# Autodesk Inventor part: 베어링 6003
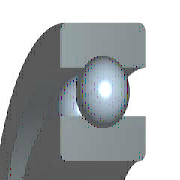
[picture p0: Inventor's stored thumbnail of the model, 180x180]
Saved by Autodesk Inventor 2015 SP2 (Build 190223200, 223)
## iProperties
IsCustomPart: 1
Created: 2009-02
Part Number: 베어링 6003
Material: 강, 연강
Description: 깊은 그루브 볼 베어링
Document SubType Name: Modeling
Standard: KS B 2023
Designer: 한국산업디자인학원
Standards Organization: KS
Language: ko-KR
Size Designation: 6003 - 17 x 35 x 10
Categories: <MemberInstance><Categories><Category DisplayName="샤프트 부품" InternalName="7f7aeb1f-a693-4053-b835-cee3144e0d98" Mnemonic="SHFT"><Category DisplayName="베어링" Inter
Density: 1 g/cm^3
Appearance: 강철
Author: 한국산업디자인학원
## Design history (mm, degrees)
sketch "스케치" dims "d0" = 4.68 (= -0.26 x WD + 0.26 x BD)
  geometry: L1 (2.66, 13)-(7.34, 13); L2 (5, 13)-(5, 10.66); L3 (5, 13)-(5, 15.34); L4 (3.261, 11.434)-(0, 11.434); L5 (0, 8.5)-(10, 8.5); L6 (3.261, 14.566)-(0, 14.566); L7 (0, 17.5)-(10, 17.5); L8 (10, 8.5)-(10, 11.434); L9 (6.739, 11.434)-(10, 11.434); L10 (6.739, 14.566)-(10, 14.566); L11 (10, 17.5)-(10, 14.566); L12 (-1.4, 0)-(8.4, 0) reference; L13 (0, -0.3)-(0, 5.3) reference
  constraints: 22 end point, 4 point on line, 2 collinear, 2 perpendicular, 2 symmetric about line, 1 midpoint, 1 parallel, 14 other
  dimensions: "d9" = 17 diameter of L5 L12 (= WD); "d11" = 35 diameter of L7 L12 (= BD); "d12" = 10 distance between parallel lines of L8 L13 (= KB); "d13" = 22.868 diameter of L9 L12 (= 0.326 x BD + 0.674 x WD)
revolve "본체" stored, may be unused: angle "d6" = 90 deg
revolve "볼" stored, may be unused: angle "d7" = 90 deg
pattern_circular "IDS_ARRAYBALL[SIMPL:T]" dims angle "d3" = 360 deg
body "Solid1"
fillet "모깎기1" dims "d1" = 0.3 (= KRS)
other parameters: "WD" = 17 [user parameter; used in 5 equation terms], "BD" = 35 [user parameter; used in 5 equation terms], "KB" = 10 [user parameter; used in 1 equation term], "KRS" = 0.3 [user parameter; used in 1 equation term], "d4" = 0, "d5" = 0, "d8" = 0, "d14" = 0, "d15" = 0, "BBA" = 0 [user parameter], "BC0" = 3250000 [user parameter], "BC" = 6050000 [user parameter], "BR" = 17.5 (= 0.5 x BD) [user parameter], "WR" = 8.5 (= 0.5 x WD) [user parameter]
